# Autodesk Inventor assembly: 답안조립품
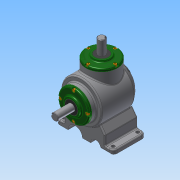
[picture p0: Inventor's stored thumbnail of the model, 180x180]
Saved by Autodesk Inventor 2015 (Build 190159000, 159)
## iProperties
Created: 2018-08
Part Number: 답안조립품
Document SubType Name: Assembly
Designer: user
Author: user
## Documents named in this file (13)
- C:\Users\user\Desktop\480807V1003\답안조립품.iam
- C:\Users\user\Desktop\480807V1003\본체.ipt
- C:\Users\user\Desktop\480807V1003\커버.ipt
- C:\Users\user\Desktop\480807V1003\오일실 17 32 8.ipt
- C:\Users\user\Desktop\480807V1003\베어링 6203.ipt
- C:\Users\user\Desktop\480807V1003\메인 축.ipt
- 메인 축.ipt
- C:\Users\user\Desktop\480807V1003\메인 베벨기어.ipt
- C:\Users\user\Desktop\480807V1003\키 5x5.ipt
- C:\Users\user\Desktop\480807V1003\서브 축.ipt
- 서브 축.ipt
- C:\Users\user\Desktop\480807V1003\키 4x4.ipt
- C:\Users\user\Desktop\480807V1003\볼트 M4.ipt
